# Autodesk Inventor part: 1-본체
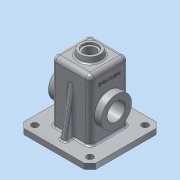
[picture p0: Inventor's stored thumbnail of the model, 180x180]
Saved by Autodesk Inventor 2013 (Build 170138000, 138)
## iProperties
Created: 2016-02
Part Number: 1-본체
Material: 알루미늄 6061
Document SubType Name: Modeling
Designer: ST1
Density: 1 g/cm^3
Author: ST1
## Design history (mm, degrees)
sketch "스케치1"
  geometry: L1 (65, -65)-(-65, -65); L2 (-65, -65)-(-65, 65); L3 (-65, 65)-(65, 65); L4 (65, 65)-(65, -65); 3 further points
  constraints: 8 end point, 2 midpoint, 2 parallel, 2 perpendicular, 1 horizontal, 1 horizontal alignment, 1 vertical alignment
  dimensions: "d0" = 130 distance of L2.end L3.end
extrude "돌출1" new body sketch "스케치1" distance "d3" = 10; taper "d4" = 0 deg
sketch "스케치2"
  geometry: L1 (-35, 35)-(35, 35); L2 (35, 35)-(35, -35); L3 (35, -35)-(-35, -35); L4 (-35, -35)-(-35, 35); 3 further points
  constraints: 8 end point, 2 midpoint, 2 parallel, 2 perpendicular, 1 horizontal, 1 horizontal alignment, 1 vertical alignment
  dimensions: "d5" = 70 distance of L1.start L1.end
extrude "돌출2" join sketch "스케치2" distance "d7" = 110; taper "d8" = 0 deg
fillet "모깎기2" dims "d18" = 8
sketch "스케치4"
  geometry: L1 (-30, 30)-(30, 30); L2 (30, 30)-(30, -30); L3 (30, -30)-(-30, -30); L4 (-30, -30)-(-30, 30); 3 further points
  constraints: 8 end point, 2 midpoint, 2 parallel, 2 perpendicular, 1 horizontal, 1 horizontal alignment, 1 vertical alignment
  dimensions: "d19" = 60 distance of L1.start L1.end
extrude "돌출3" cut sketch "스케치4" distance "d21" = 115; taper "d22" = 0 deg
sketch "스케치3"
  geometry: L1 (-35, 10)-(-35, 120) reference; L2 (65, 10)-(-65, 10) reference; L3 (-35, 95.069)-(-50, 10); L4 (-65, 0)-(-65, 10) reference; 1 further point
  constraints: 2 end point, 2 point on line
  dimensions: "d9" = 10 deg angle of L4 L3; "d10" = 15 distance of L2.end L3.end
feature "리브1" sketch "스케치3" dims "d11" = 1, "d12" = 10, "d13" = 0, "d14" = 0, "d15" = 1, "d16" = 1
sketch "스케치6"
  geometry: L1 (10, 100)-(10, -30) reference; C1 r 27.5 at (-45, 35); 2 further points
  constraints: 1 centre point, 1 horizontal alignment, 1 midpoint
  dimensions: "d27" = 55 distance from line of L1 C1.centre; "d28" = 55 diameter of C1
extrude "돌출4" join sketch "스케치6" distance "d29" = 13; taper "d30" = 0 deg
sketch "스케치7"
  geometry: C1 r 27.5 at (-55, 30) reference; 1 further point
extrude "돌출5" join sketch "스케치7" distance "d31" = 7; taper "d32" = -45 deg
sketch "스케치8"
  geometry: C1 r 27.5 at (0, 0) reference; C2 r 16 at (0, 0); 1 further point
  constraints: 1 centre point, 1 coincident
  dimensions: "d33" = 32 diameter of C2
extrude "돌출6" cut sketch "스케치8" stored distance "d35" = 7; taper "d36" = 0 deg
fillet "모깎기5" dims "d37" = 8
fillet "모깎기6" dims "d38" = 3
fillet "모깎기7" dims "d39" = 0.5
fillet "모깎기8" dims "d40" = 0.5
sketch "스케치9"
  geometry: C1 r 20 at (0, 0); 1 further point
  constraints: 1 centre point, 1 coincident
  dimensions: "d41" = 40 diameter of C1
extrude "돌출7" join sketch "스케치9" distance "d43" = 10; taper "d44" = -10 deg
sketch "스케치10"
  geometry: C1 r 18.237 at (0, 0) reference; C2 r 14 at (0, 0)
  constraints: 1 centre point, 1 coincident
  dimensions: "d45" = 28 diameter of C2
extrude "돌출8" cut sketch "스케치10" distance "d47" = 4; taper "d48" = 0 deg
sketch "스케치11"
  geometry: C1 r 14 at (0, 0) reference; C2 r 10.5 at (0, 0)
  constraints: 1 centre point, 1 coincident
  dimensions: "d49" = 21 diameter of C2
extrude "돌출9" cut sketch "스케치11" stored distance "d51" = 4; taper "d52" = 0 deg
fillet "모깎기9" dims "d53" = 3
chamfer "모따기1" distance "d54" = 10; stored, may be unused: second distance "d55" = 2, angle "d56" = 45 deg
sketch "스케치12"
  geometry: L1 (-65, 55)-(-65, -55) reference; L2 (55, 65)-(-55, 65) reference; C1 r 6 at (-50, -50); C2 r 6 at (-50, 50); C3 r 6 at (50, 50); C4 r 6 at (50, -50); 1 further point
  constraints: 4 centre point, 3 equal radius, 2 horizontal alignment, 2 vertical alignment
  dimensions: "d57" = 12 diameter of C2; "d59" = 15 distance from line of L2 C2.centre; "d60" = 100 distance of C1.centre C2.centre; "d61" = 15 distance from line of L1 C2.centre; "d62" = 100 distance of C3.centre C2.centre
extrude "돌출10" cut sketch "스케치12" stored distance "d63" = 4; taper "d64" = 0 deg
chamfer "모따기2" distance "d65" = 1; stored, may be unused: second distance "d66" = 2, angle "d67" = 45 deg
fillet "모깎기10" dims "d68" = 3
fillet "모깎기11" dims "d69" = 3
sketch "스케치13"
  geometry: L1 (99, 62)-(0, 62) reference; L2 (-18, 8.763)-(-18, 45.237) reference; 2 further points
  constraints: 1 other
  dimensions: "d70" = 35 distance from line of L1 point (12, 27); "d71" = 30 distance from line of L2 point (12, 27)
feature "엠보싱1" sketch "스케치13" dims "d0" = 130, "d9" = 10 deg, "d10" = 15, "d72" = 0.5, "d73" = 0
node "솔리드1"
mirror "대칭1"
mirror "대칭2"
mirror "대칭3"
